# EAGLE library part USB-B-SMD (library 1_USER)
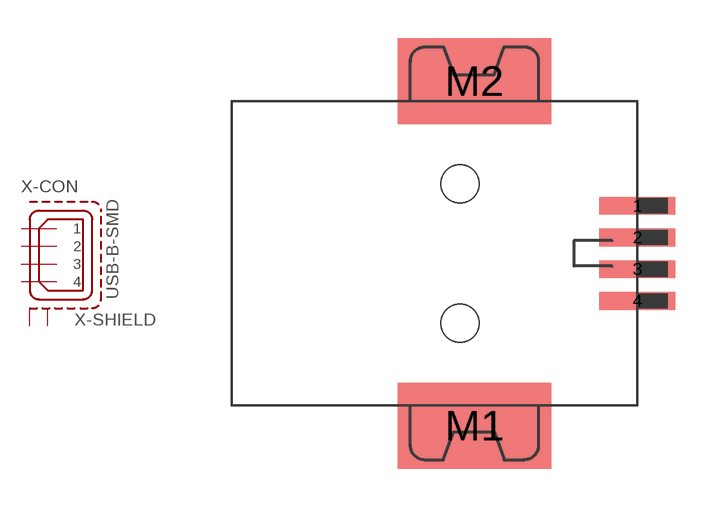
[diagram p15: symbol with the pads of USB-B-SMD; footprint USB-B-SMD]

Designator prefix X; gates -CON=USB-B -SHIELD=USB-B-SHIELD

## USB-B-SMD  [USB-B-SMD]
1  -CON:1  in
2  -CON:2  in
3  -CON:3  in
4  -CON:4  in
M1  -SHIELD:S1  pas
M2  -SHIELD:S2  pas

## Footprint USB-B-SMD (pad centres in mm)
smd 3 x 0.7: 1 7,1.875; 2 7,0.625; 3 7,-0.625; 4 7,-1.875
smd 6.04 x 3.4: M1 0.58,-6.8; M2 0.58,6.8
hole 1.5 at 0,-2.75
hole 1.5 at 0,2.75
